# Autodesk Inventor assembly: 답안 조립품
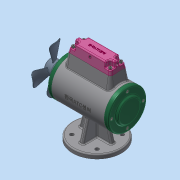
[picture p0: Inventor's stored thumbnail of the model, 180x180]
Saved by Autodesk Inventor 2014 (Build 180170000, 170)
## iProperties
Created: 2023-01
Part Number: 답안 조립품
Document SubType Name: Assembly
Designer: dg
Mass: 3179.56 g
Surface Area: 2659.3 cm^2
Volume: 945.987 cm^3
Density: 3.3611 g/cm^3
Author: dg
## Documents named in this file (19)
- C:\Users\dg\Desktop\630106V1017 (1)\답안 조립품.iam
- C:\Users\dg\Desktop\630106V1017 (1)\본체.ipt
- C:\Users\dg\Desktop\630106V1017 (1)\축.ipt
- C:\Users\dg\Desktop\630106V1017 (1)\키 5 x 5 x 18.ipt
- C:\Users\dg\Desktop\630106V1017 (1)\베어링 6203.ipt
- C:\Users\dg\Desktop\630106V1017 (1)\뒤커버.ipt
- C:\Users\dg\Desktop\630106V1017 (1)\앞커버.ipt
- C:\Users\dg\Desktop\630106V1017 (1)\볼트 M4 x 12.ipt
- C:\Users\dg\Desktop\630106V1017 (1)\오일실 17 30 8.ipt
- C:\Users\dg\Desktop\630106V1017 (1)\멈춤나사 M4 x 8.ipt
- C:\Users\dg\Desktop\630106V1017 (1)\팬날개.ipt
- 팬날개.ipt
- C:\Users\dg\Desktop\630106V1017 (1)\부시.ipt
- C:\Users\dg\Desktop\630106V1017 (1)\헤더커버.ipt
- C:\Users\dg\Desktop\630106V1017 (1)\볼트 M4 x 16.ipt
- C:\Users\dg\Desktop\630106V1017 (1)\가변스프링1.ipt
- C:\Users\dg\Desktop\630106V1017 (1)\슬라이드.ipt
- C:\Users\dg\Desktop\630106V1017 (1)\가변스프링2.ipt
- C:\Users\dg\Desktop\630106V1017 (1)\가변스프링3.ipt
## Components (4 placed, 4 different names)
1. 헤더커버:1
2. 가변스프링1:1
3. 가변스프링2:1
4. 가변스프링3:1
